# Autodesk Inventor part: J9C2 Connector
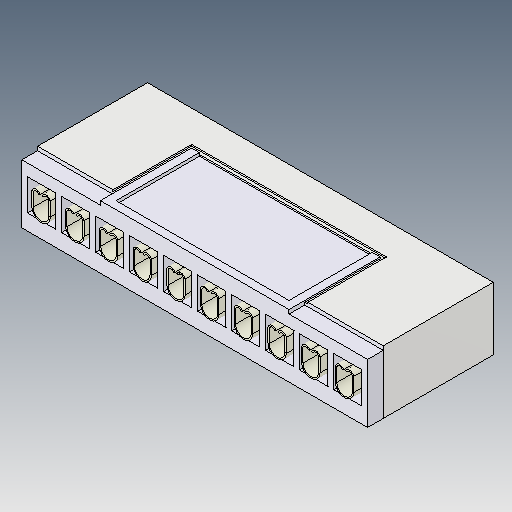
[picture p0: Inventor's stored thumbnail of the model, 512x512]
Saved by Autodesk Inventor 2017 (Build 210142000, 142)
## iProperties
Created: 2005-12
Part Number: J9C2 Connector
Material: Generic
Document SubType Name: Modeling
Designer: DanielSeverino
Density: 1 g/cm^3
Appearance: Default
Author: DanielSeverino
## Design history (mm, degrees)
feature "Solid1"
body "Solid2"
